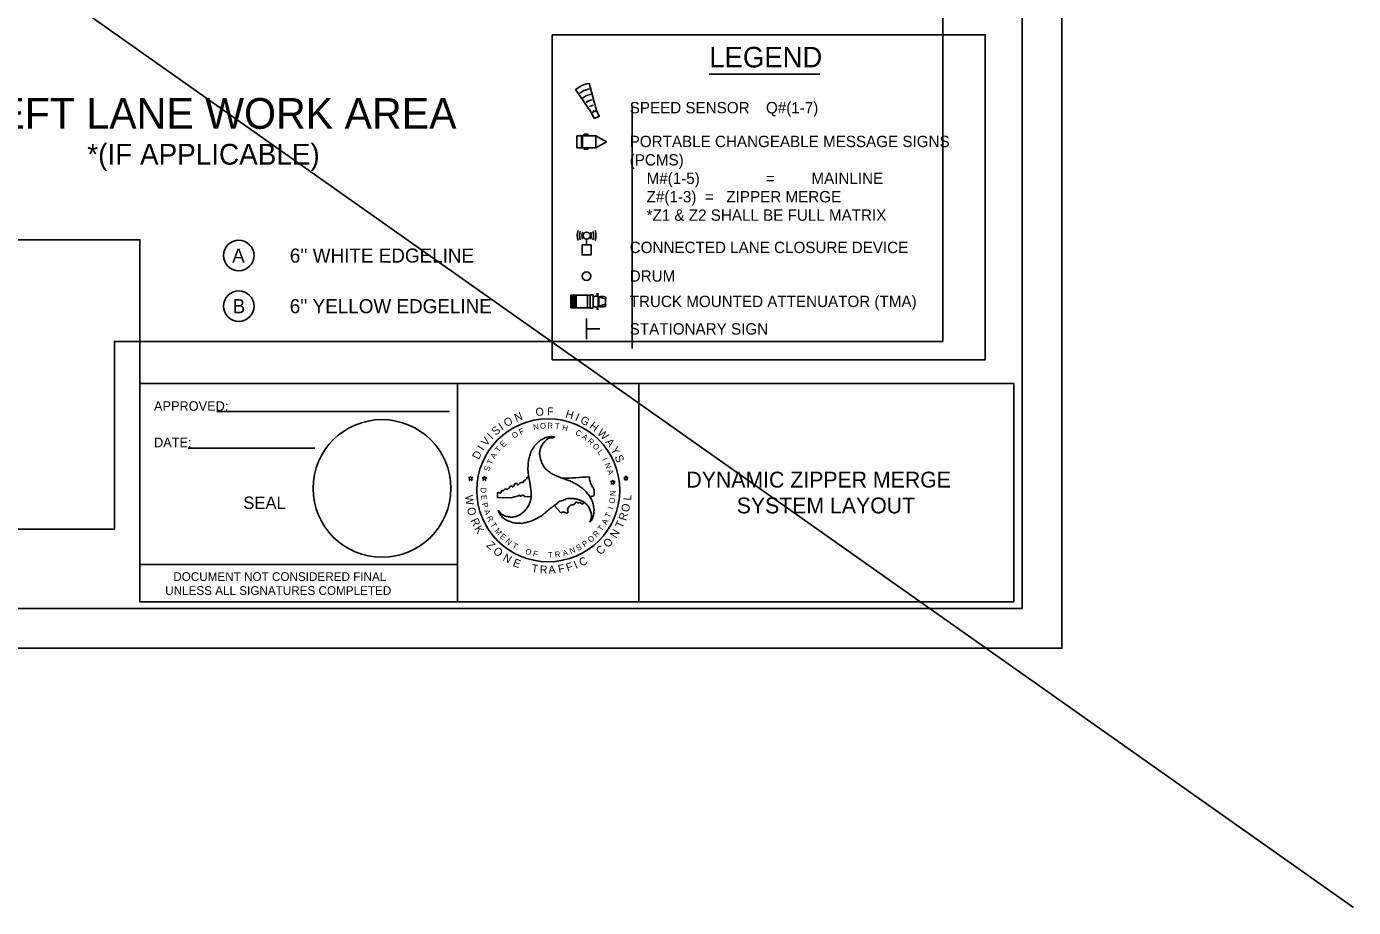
# Model space of a CAD drawing. Extents: x 1379436 to 1387057, y 792703 to 795604.
# Drawn here: x 1381631 to 1382883, y 792987 to 793820 of the extents above; entities that cross this region are included whole.
import ezdxf

# ---------------------------------------------------------------- set-up
doc = ezdxf.new("R2010")
doc.units = 0
for name, color, linetype in [('Black Area Fill Shapes', 7, 'Continuous'), ('Default', 7, 'Continuous'), ('DEV BORDER CELL', 7, 'Continuous'), ('DEV CMS PLAN VIEW CELL', 7, 'Continuous'), ('DEV DOT SWIRL SEAL CELL', 7, 'Continuous'), ('DEV DRUM PLAN VIEW CELL', 7, 'Continuous'), ('DEV PRELIMINARY STAMP CELL', 7, 'Continuous'), ('DEV TRUCK MOUNTED IMPACT ATTENUATOR CELL', 7, 'Continuous'), ('Scratch_Level_0', 7, 'Continuous'), ('Sheet Plot Border Outside CELL', 7, 'Continuous'), ('Sheet Sticker Exception Certification CELL', 7, 'Continuous'), ('TCP Linework', 7, 'Continuous'), ('Text', 7, 'Continuous')]:
    doc.layers.add(name, color=color, linetype=linetype)

msp = doc.modelspace()

# ---------------------------------------------------------------- linework, layer by layer
at = {"layer": 'Black Area Fill Shapes'}
msp.add_lwpolyline([(1382166.8, 793732.5), (1382164.2, 793738), (1382169, 793740.2), (1382171.6, 793734.7)], close=True, dxfattribs=at)
at = {"layer": 'Default'}
for p, q in [((1379436.3, 795421.7), (1382883.5, 792987.4)), ((1380320.7, 793618), (1381738.3, 793618)), ((1381738, 793482.4), (1381738, 793618))]:
    msp.add_line(p, q, dxfattribs=at)
for centre in [(1381831.4, 793603.2), (1381831.4, 793555.4)]:
    msp.add_circle(centre, 14.4, dxfattribs=at)
at = {"layer": 'DEV BORDER CELL'}
for p, q in [((1381810.8, 793455.8), (1382030.3, 793455.8)), ((1382038, 793447.1), (1382038, 793276.1)), ((1381783.6, 793421.2), (1381903.3, 793421.2))]:
    msp.add_line(p, q, dxfattribs=at)
for points in [[(1382570.8, 794844.7), (1380320.7, 794844.7), (1380320.7, 793269.7), (1382570.8, 793269.7)], [(1381738, 793482.4), (1382038, 793482.4), (1382038, 793276.1), (1381738, 793276.1)], [(1382038, 793482.4), (1382209, 793482.4), (1382209, 793276.1), (1382038, 793276.1)], [(1382563, 793482.4), (1382209, 793482.4), (1382209, 793276.1), (1382563, 793276.1)]]:
    msp.add_lwpolyline(points, close=True, dxfattribs=at)
msp.add_circle((1381966.6, 793383.2), 65, dxfattribs=at)
at = {"layer": 'DEV CMS PLAN VIEW CELL'}
for p, q in [((1382150.6, 793716.4), (1382168.4, 793716.4)), ((1382150.6, 793704.8), (1382150.6, 793716.4)), ((1382150.6, 793716.4), (1382150.6, 793704.8)), ((1382154.8, 793704.8), (1382154.8, 793716.4)), ((1382155.7, 793704.8), (1382155.7, 793716.4)), ((1382157.3, 793717.8), (1382161, 793717.8)), ((1382157.3, 793716.7), (1382161, 793716.7)), ((1382168.4, 793704.8), (1382168.4, 793716.4)), ((1382168.4, 793716.4), (1382178.4, 793710.6)), ((1382150.6, 793704.8), (1382168.4, 793704.8)), ((1382157.3, 793704.6), (1382161, 793704.6)), ((1382157.3, 793703.5), (1382161, 793703.5)), ((1382168.4, 793704.8), (1382178.4, 793710.6))]:
    msp.add_line(p, q, dxfattribs=at)
msp.add_circle((1382178.5, 793710.6), 0.102, dxfattribs=at)
for centre, start, end in [((1382158, 793717.3), 142.0883, 217.9117), ((1382160.3, 793717.3), 322.0883, 37.9117), ((1382158, 793704.1), 142.0883, 217.9117), ((1382160.3, 793704.1), 322.0883, 37.9117)]:
    msp.add_arc(centre, 0.852, start, end, dxfattribs=at)
at = {"layer": 'DEV DOT SWIRL SEAL CELL'}
for p, q in [((1382048.1, 793393.4), (1382049.4, 793392.4)), ((1382049.7, 793393.4), (1382048.1, 793393.4)), ((1382049.4, 793392.4), (1382049, 793390.8)), ((1382049, 793390.8), (1382050.2, 793391.8)), ((1382050.2, 793394.9), (1382049.7, 793393.4)), ((1382050.8, 793393.4), (1382050.2, 793394.9)), ((1382050.2, 793391.8), (1382051.6, 793390.8)), ((1382050.2, 793391.8), (1382051.6, 793390.8)), ((1382052.4, 793393.4), (1382050.8, 793393.4)), ((1382051.1, 793392.4), (1382052.4, 793393.4)), ((1382051.1, 793392.4), (1382052.4, 793393.4)), ((1382051.6, 793390.8), (1382051.1, 793392.4)), ((1382051.6, 793390.8), (1382051.1, 793392.4)), ((1382062.8, 793393.3), (1382061.1, 793393.3)), ((1382061.1, 793393.3), (1382062.5, 793392.4)), ((1382062.5, 793392.4), (1382062, 793390.8)), ((1382062, 793390.8), (1382063.2, 793391.8)), ((1382063.2, 793394.8), (1382062.8, 793393.3)), ((1382063.8, 793393.3), (1382063.2, 793394.8)), ((1382063.2, 793391.8), (1382064.6, 793390.8)), ((1382065.4, 793393.3), (1382063.8, 793393.3)), ((1382064.1, 793392.4), (1382065.4, 793393.3)), ((1382064.6, 793390.8), (1382064.1, 793392.4)), ((1382183.9, 793389.6), (1382182.3, 793389.6)), ((1382182.3, 793389.6), (1382183.6, 793388.6)), ((1382183.6, 793388.6), (1382183.1, 793387.1)), ((1382183.1, 793387.1), (1382184.4, 793388)), ((1382184.4, 793391.1), (1382183.9, 793389.6)), ((1382184.9, 793389.6), (1382184.4, 793391.1)), ((1382184.4, 793388), (1382185.7, 793387.1)), ((1382186.6, 793389.6), (1382184.9, 793389.6)), ((1382185.2, 793388.6), (1382186.6, 793389.6)), ((1382185.7, 793387.1), (1382185.2, 793388.6)), ((1382196.3, 793393.6), (1382194.7, 793393.6)), ((1382194.7, 793393.6), (1382196, 793392.6)), ((1382196, 793392.6), (1382195.5, 793391)), ((1382195.5, 793391), (1382196.8, 793392)), ((1382196.8, 793395.1), (1382196.3, 793393.6)), ((1382197.4, 793393.6), (1382196.8, 793395.1)), ((1382196.8, 793392), (1382198.1, 793391)), ((1382199, 793393.6), (1382197.4, 793393.6)), ((1382197.7, 793392.6), (1382199, 793393.6)), ((1382198.1, 793391), (1382197.7, 793392.6)), ((1382075.6, 793374.7), (1382075.7, 793378.7)), ((1382088.2, 793374.2), (1382075.6, 793374.7)), ((1382095.4, 793376.3), (1382088.2, 793374.2)), ((1382101, 793375.5), (1382107.3, 793375.4)), ((1382129.1, 793367.1), (1382135.5, 793360.1))]:
    msp.add_line(p, q, dxfattribs=at)
for start, end in [(265.6785, 265.9762), (271.2035, 275.3236)]:
    msp.add_arc((1382129.7, 793742.5), 349.8, start, end, dxfattribs=at)
for points in [[(1382076.2, 793362.5), (1382078.8, 793359.5), (1382082.1, 793357.4), (1382085.9, 793356.4), (1382090.1, 793356.2), (1382094.4, 793357.2), (1382097.2, 793358.7), (1382098.5, 793359.6), (1382100.5, 793361.3), (1382102, 793362.9), (1382104.5, 793366.4), (1382106.5, 793370.6), (1382107.3, 793375.4), (1382107.3, 793375.8), (1382107.3, 793380.3), (1382106.7, 793384.9), (1382106, 793389.3), (1382105.2, 793393.8), (1382104.5, 793398.3), (1382104.4, 793402.7), (1382104.7, 793407.7), (1382105.4, 793412), (1382106.8, 793416.5), (1382107.6, 793418.6), (1382108.6, 793420.3), (1382111.3, 793424.2), (1382114.7, 793427.5), (1382116.9, 793429.2), (1382119.1, 793430.3), (1382119.4, 793430.5), (1382123.7, 793431.9), (1382127.9, 793432), (1382129.3, 793431.7)], [(1382129.4, 793431.8), (1382129.3, 793431.7), (1382125.4, 793430.9), (1382121.9, 793429.1), (1382119.2, 793426.4), (1382116.9, 793422.9), (1382115.6, 793418.6), (1382115.4, 793415.4), (1382115.7, 793413.9), (1382116.1, 793411.2), (1382116.7, 793409.2), (1382118.6, 793405.2), (1382121.2, 793401.5), (1382125, 793398.4), (1382125.3, 793398.1), (1382129.2, 793395.9), (1382133.5, 793394.1), (1382137.6, 793392.5), (1382141.9, 793391), (1382146.2, 793389.3), (1382150, 793387.2), (1382154.3, 793384.4), (1382157.6, 793381.6), (1382160.7, 793378.2), (1382162.2, 793376.5), (1382163.1, 793374.7), (1382165.3, 793370.5), (1382166.3, 793365.9), (1382166.7, 793363.1), (1382166.6, 793360.7), (1382166.6, 793360.3), (1382165.6, 793355.9), (1382163.6, 793352.2), (1382162.7, 793351.2)], [(1382075.7, 793378.7), (1382075.6, 793379.1), (1382076.3, 793379.5), (1382078.2, 793378.7), (1382079.1, 793379.5), (1382079, 793380.3), (1382079.8, 793381.1), (1382081.1, 793380.9), (1382082.2, 793382.3), (1382083.3, 793382.6), (1382085.5, 793382.6), (1382088.2, 793385.3), (1382089.3, 793385.5), (1382089.6, 793384.7), (1382090.3, 793384.6), (1382091.5, 793386.8), (1382091.8, 793387.1), (1382093.8, 793388), (1382094.3, 793387.5), (1382094.5, 793386.6), (1382094.8, 793386.4), (1382095.5, 793386.9), (1382096.4, 793388), (1382098.1, 793388.9), (1382100.1, 793388.7), (1382100.4, 793390.3), (1382102.7, 793391.8), (1382103.2, 793392.7), (1382103.3, 793393.7)], [(1382162.6, 793375.8), (1382166.3, 793376.3), (1382166.8, 793379.2), (1382166.9, 793381.7), (1382165.3, 793384.5), (1382163.1, 793389.7), (1382162.1, 793394.2)], [(1382162.7, 793351.2), (1382164, 793354.9), (1382164.2, 793358.8), (1382163.1, 793362.5), (1382161.2, 793366.3), (1382158.2, 793369.5), (1382155.6, 793371.3), (1382154.1, 793371.8), (1382151.6, 793372.8), (1382149.4, 793373.3), (1382145.2, 793373.7), (1382140.5, 793373.3), (1382136, 793371.5), (1382135.6, 793371.4), (1382131.8, 793369.1), (1382128.1, 793366.3), (1382124.6, 793363.6), (1382121.1, 793360.6), (1382117.5, 793357.7), (1382113.8, 793355.4), (1382109.2, 793353.1), (1382105.2, 793351.7), (1382100.7, 793350.6), (1382098.4, 793350.2), (1382096.4, 793350.3), (1382091.7, 793350.6), (1382087.2, 793351.9), (1382084.6, 793353), (1382082.6, 793354.3), (1382082.2, 793354.5), (1382078.9, 793357.6), (1382076.7, 793361.1), (1382076.2, 793362.5)], [(1382101, 793375.5), (1382100.4, 793376.5), (1382099.4, 793376.8), (1382098, 793376), (1382097, 793376.1), (1382095.9, 793376.9), (1382095.4, 793376.3)], [(1382135.5, 793360.1), (1382138.1, 793360.8), (1382140.2, 793360), (1382141.2, 793359.9), (1382142.1, 793360.5), (1382141.8, 793363.7), (1382142.5, 793365.2), (1382146, 793367.7), (1382148.1, 793368.2), (1382149.7, 793370.1), (1382150.3, 793370.1), (1382151.3, 793369.5), (1382153.4, 793369.9), (1382155.2, 793368.5), (1382156.2, 793368.6), (1382157, 793370.2)]]:
    msp.add_spline(points, degree=3, dxfattribs=at)
at = {"layer": 'DEV DRUM PLAN VIEW CELL'}
msp.add_circle((1382159.7, 793583.7), 4.08, dxfattribs=at)
msp.add_circle((1382159.7, 793583.7), 4.08, dxfattribs=at)
at = {"layer": 'DEV TRUCK MOUNTED IMPACT ATTENUATOR CELL'}
for p, q in [((1382144.7, 793565.6), (1382163.2, 793565.6)), ((1382144.7, 793553.7), (1382144.7, 793565.6)), ((1382144.7, 793565.6), (1382144.7, 793563.4)), ((1382144.7, 793565.6), (1382144.7, 793563.4)), ((1382144.7, 793565.6), (1382144.7, 793563.4)), ((1382144.7, 793565.6), (1382144.7, 793563.4)), ((1382144.7, 793563.4), (1382144.7, 793565.6)), ((1382144.7, 793565.6), (1382146.8, 793565.6)), ((1382146.8, 793565.6), (1382144.7, 793563.4)), ((1382144.7, 793561.5), (1382148.4, 793565.6)), ((1382150, 793565.6), (1382144.7, 793559.7)), ((1382144.7, 793559.7), (1382144.7, 793561.5)), ((1382146.4, 793559.7), (1382150, 793563.8)), ((1382150, 793561.9), (1382148, 793559.7)), ((1382148.4, 793565.6), (1382150, 793565.6)), ((1382150, 793553.7), (1382150, 793565.6)), ((1382150, 793563.8), (1382150, 793561.9)), ((1382160.7, 793559.7), (1382160.7, 793565.6)), ((1382163.2, 793559.7), (1382163.2, 793565.6)), ((1382166, 793559.7), (1382166, 793565.6)), ((1382169.8, 793566), (1382169.8, 793567.5)), ((1382170.1, 793564.6), (1382170.1, 793567.5)), ((1382170.3, 793564.6), (1382170.3, 793567.5)), ((1382170.7, 793559.7), (1382170.7, 793564)), ((1382171.2, 793564), (1382177.6, 793562.2)), ((1382171.2, 793559.7), (1382171.2, 793564)), ((1382177.6, 793559.7), (1382177.6, 793562.2)), ((1382144.7, 793559.7), (1382150, 793553.7)), ((1382144.7, 793557.9), (1382144.7, 793559.7)), ((1382148.4, 793553.7), (1382144.7, 793557.9)), ((1382144.7, 793556), (1382144.7, 793553.7)), ((1382146.8, 793553.7), (1382144.7, 793556)), ((1382144.7, 793553.7), (1382163.2, 793553.7)), ((1382144.7, 793553.7), (1382146.8, 793553.7)), ((1382150, 793555.6), (1382146.4, 793559.7)), ((1382148.1, 793559.7), (1382150, 793557.5)), ((1382150, 793553.7), (1382148.4, 793553.7)), ((1382150, 793557.5), (1382150, 793555.6)), ((1382160.7, 793559.7), (1382160.7, 793553.7)), ((1382163.2, 793559.7), (1382163.2, 793553.7)), ((1382166, 793559.7), (1382166, 793553.7)), ((1382169.8, 793553.3), (1382169.8, 793551.9)), ((1382170.1, 793554.8), (1382170.1, 793551.9)), ((1382170.3, 793554.8), (1382170.3, 793551.9)), ((1382170.7, 793559.7), (1382170.7, 793555.4)), ((1382171.2, 793559.7), (1382171.2, 793555.4)), ((1382171.2, 793555.4), (1382177.6, 793557.2)), ((1382177.6, 793559.7), (1382177.6, 793557.2))]:
    msp.add_line(p, q, dxfattribs=at)
for centre in [(1382176, 793563.1), (1382176, 793556.3)]:
    msp.add_arc(centre, 1.79, 331.8801, 28.1199, dxfattribs=at)
for centre, major_axis, ratio, start_param, end_param in [((1382164.6, 793565.6), (1.41, 0), 0.269913, 6.283185, 9.424778), ((1382168.4, 793563.7), (2.37, 0.29), 0.503092, 0, 3.141593), ((1382174.4, 793563.9), (3.23, -0.04), 0.2034, 6.283185, 9.424778), ((1382164.6, 793553.7), (1.41, 0), 0.269913, 3.141593, 6.283185), ((1382168.4, 793555.7), (2.37, -0.29), 0.503092, 3.141593, 6.283185), ((1382174.4, 793555.4), (3.23, 0.04), 0.2034, 3.141593, 6.283185)]:
    msp.add_ellipse(centre, major_axis=major_axis, ratio=ratio, start_param=start_param, end_param=end_param, dxfattribs=at)
at = {"layer": 'Scratch_Level_0'}
msp.add_line((1382202.6, 793515.5), (1382202.6, 793745), dxfattribs=at)
msp.add_lwpolyline([(1382495.8, 794769.7), (1380395.7, 794769.7), (1380395.7, 793344.7), (1381714, 793344.7), (1381714, 793522.1), (1382495.8, 793522.1)], close=True, dxfattribs=at)
at = {"layer": 'Sheet Plot Border Outside CELL'}
msp.add_lwpolyline([(1380076.3, 793232.2), (1382608.3, 793232.2), (1382608.3, 794882.2), (1380076.3, 794882.2)], close=True, dxfattribs=at)
at = {"layer": 'Sheet Sticker Exception Certification CELL'}
for p, q in [((1381738, 793276.1), (1381738, 793311.4)), ((1381738, 793311.4), (1382038, 793311.4)), ((1382038, 793311.3), (1382038, 793276.1)), ((1382038, 793276.1), (1381738, 793276.1))]:
    msp.add_line(p, q, dxfattribs=at)
at = {"layer": 'TCP Linework'}
for p, q in [((1382159.7, 793543.6), (1382159.7, 793524.3)), ((1382159.7, 793533.9), (1382172.2, 793533.9))]:
    msp.add_line(p, q, dxfattribs=at)
msp.add_lwpolyline([(1382127.3, 793811.7), (1382536, 793811.7), (1382536, 793504.7), (1382127.3, 793504.7)], close=True, dxfattribs=at)
at = {"layer": 'Text'}
for p, q in [((1382275.5, 793774.4), (1382379.7, 793774.4)), ((1382169, 793740.2), (1382162, 793765.9)), ((1382164.2, 793738), (1382149.3, 793760)), ((1382159.7, 793613.2), (1382159.7, 793618.7))]:
    msp.add_line(p, q, dxfattribs=at)
msp.add_lwpolyline([(1382155.5, 793613.2), (1382163.9, 793613.2), (1382163.9, 793603.7), (1382155.5, 793603.7)], close=True, dxfattribs=at)
for centre, radius in [((1382159.7, 793622), 3.3), ((1382123.5, 793381.4), 67.5)]:
    msp.add_circle(centre, radius, dxfattribs=at)
for centre, radius, start, end in [((1382167.1, 793738), 28.3, 100.4731, 129.0092), ((1382167.1, 793738), 23.1, 100.4731, 129.0092), ((1382167.1, 793738), 17.9, 100.4731, 129.0092), ((1382167.1, 793738), 12.6, 100.4731, 129.0092), ((1382167.1, 793738), 7.36, 100.4731, 129.0092), ((1382167.1, 793738), 2.12, 100.4731, 129.0092), ((1382165.5, 793622), 14.6, 161.0657, 198.9343), ((1382165.5, 793622), 12.4, 161.0657, 198.9343), ((1382165.5, 793622), 10.2, 161.0657, 198.9343), ((1382153.9, 793622), 10.2, 341.0657, 18.9343), ((1382153.9, 793622), 12.4, 341.0657, 18.9343), ((1382153.9, 793622), 14.6, 341.0657, 18.9343)]:
    msp.add_arc(centre, radius, start, end, dxfattribs=at)

# ---------------------------------------------------------------- texts
at = {"layer": 'Default'}
for s, height, p in [('LEFT LANE WORK AREA', 29.027, (1381581.9, 793722.9)), ('*(IF APPLICABLE)', 19.675, (1381688.5, 793689)), ('DYNAMIC ZIPPER MERGE', 15, (1382253.9, 793384)), ('SYSTEM LAYOUT', 15, (1382301.4, 793359.6))]:
    msp.add_text(s, height=height, dxfattribs=at).set_placement(p)
at = {"layer": 'DEV BORDER CELL'}
for s, p in [('APPROVED:  ', (1381751.4, 793456.5)), ('DATE:  ', (1381751.4, 793422.1))]:
    msp.add_text(s, height=9, dxfattribs=at).set_placement(p)
at = {"layer": 'DEV DOT SWIRL SEAL CELL'}
for s, height, rotation, p in [('O', 7.56, 30.0935, (1382084.1, 793440.9)), ('N', 7.56, 21.5861, (1382093.3, 793445.9)), ('O', 7.56, 5.7649, (1382111.9, 793451.5)), ('F', 7.56, 357.2575, (1382122.3, 793452.3)), ('H', 7.56, 343.454, (1382139.2, 793450.4)), ('I', 7.56, 335.804, (1382148.2, 793447.6)), ('G', 7.56, 331.5167, (1382153, 793445.5)), ('I', 7.56, 44.8722, (1382070.4, 793429.1)), ('S', 7.56, 40.5848, (1382074, 793432.8)), ('I', 7.56, 34.3808, (1382079.8, 793437.8)), ('O', 5.44, 29.335, (1382091, 793430.1)), ('F', 5.44, 24.2569, (1382097.4, 793433.7)), ('N', 5.44, 9.0227, (1382109.7, 793438.3)), ('O', 5.44, 3.9446, (1382115.9, 793439.4)), ('R', 5.44, 358.8665, (1382122.6, 793439.8)), ('H', 5.44, 343.6322, (1382136.2, 793438.5)), ('C', 5.44, 333.4761, (1382148.6, 793434.2)), ('H', 7.56, 323.4632, (1382161.7, 793440.6)), ('W', 7.56, 315.8133, (1382169.2, 793434.9)), ('I', 7.56, 55.8679, (1382062.3, 793418.2)), ('V', 7.56, 51.5806, (1382065.2, 793422.6)), ('T', 5.44, 49.6473, (1382076.8, 793416.6)), ('E', 5.44, 44.5692, (1382081.1, 793421.6)), ('A', 5.44, 323.3199, (1382154.7, 793431)), ('R', 5.44, 318.2418, (1382160, 793427.1)), ('O', 5.44, 313.1637, (1382164.8, 793422.8)), ('A', 7.56, 306.7762, (1382176.9, 793427)), ('Y', 7.56, 299.7484, (1382182.1, 793420)), ('D', 7.56, 63.459, (1382058, 793409.9)), ('T', 5.44, 64.8816, (1382070.1, 793405)), ('A', 5.44, 59.8035, (1382073, 793410.7)), ('L', 5.44, 308.0856, (1382169.6, 793417.3)), ('I', 5.44, 297.9295, (1382174.2, 793410.5)), ('S', 7.56, 293.2249, (1382186, 793413)), ('S', 5.44, 69.9597, (1382067.7, 793398.8)), ('N', 5.44, 292.8514, (1382176.5, 793406.1)), ('A', 5.44, 287.7733, (1382178.9, 793400.1)), ('D', 5.44, 270.272, (1382059.7, 793384)), ('E', 5.44, 275.3501, (1382059.9, 793376.7)), ('O', 5.44, 82.9269, (1382186.2, 793368.6)), ('N', 5.44, 87.733, (1382187.2, 793375.9)), ('P', 5.44, 285.5063, (1382060.8, 793368.9)), ('A', 5.44, 290.5843, (1382062.6, 793362.2)), ('T', 5.44, 67.6926, (1382181.6, 793354.9)), ('I', 5.44, 72.7707, (1382184.6, 793363)), ('R', 5.44, 295.6624, (1382065.1, 793355.7)), ('T', 5.44, 300.7405, (1382068.5, 793349.1)), ('T', 5.44, 52.4584, (1382173.9, 793342.2)), ('A', 5.44, 62.6145, (1382178.3, 793348.4)), ('M', 5.44, 310.8967, (1382072.4, 793342.9)), ('E', 5.44, 315.9748, (1382077.4, 793337.2)), ('N', 5.44, 321.0529, (1382082.6, 793332.5)), ('O', 5.44, 42.3022, (1382163.7, 793331.7)), ('R', 5.44, 47.3803, (1382169, 793336.6)), ('T', 5.44, 331.209, (1382088.9, 793327.6)), ('O', 5.44, 341.3652, (1382101.3, 793321.6)), ('F', 5.44, 346.4433, (1382108.6, 793319.4)), ('T', 5.44, 1.6775, (1382123.3, 793317.6)), ('R', 5.44, 6.7556, (1382130, 793317.9)), ('A', 5.44, 16.9118, (1382137.9, 793319.1)), ('N', 5.44, 21.9899, (1382144.8, 793321.2)), ('S', 5.44, 27.068, (1382151.4, 793324)), ('P', 5.44, 32.146, (1382157.6, 793327.4))]:
    msp.add_text(s, height=height, rotation=rotation, dxfattribs=at).set_placement(p)
at = {"layer": 'DEV PRELIMINARY STAMP CELL'}
msp.add_text('SEAL', height=11.72, dxfattribs=at).set_placement((1381835.7, 793363.8))
at = {"layer": 'Sheet Sticker Exception Certification CELL'}
for s, p in [('DOCUMENT NOT CONSIDERED FINAL', (1381769.6, 793295.8)), ('UNLESS ALL SIGNATURES COMPLETED', (1381762, 793282.6))]:
    msp.add_text(s, height=8.25, dxfattribs=at).set_placement(p)
at = {"layer": 'Text'}
for s, height, p in [('LEGEND', 19.39, (1382275.5, 793780.9)), ('SPEED SENSOR', 10.722, (1382200.4, 793737.5)), ('Q#(1-7)', 10.72, (1382329, 793737.5)), ('PORTABLE CHANGEABLE MESSAGE SIGNS ', 10.722, (1382200.4, 793705.6)), ('(PCMS)', 10.72, (1382200.4, 793688.2)), ('    M#(1-5)', 10.722, (1382200.4, 793670.8)), ('=', 10.7, (1382329, 793670.8)), ('MAINLINE', 10.72, (1382371.9, 793670.8)), ('    Z#(1-3)  =   ZIPPER MERGE', 10.722, (1382200.4, 793653.4)), ('    *Z1 & Z2 SHALL BE FULL MATRIX    ', 10.722, (1382200.4, 793636)), ('CONNECTED LANE CLOSURE DEVICE', 10.722, (1382200.4, 793605.5)), ('A', 13.3, (1381825.2, 793596.5)), ("6'' WHITE EDGELINE", 13.31, (1381879.6, 793596.5)), ('DRUM', 10.72, (1382200.4, 793578.5)), ('B', 13.3, (1381825.7, 793548.7)), ("6'' YELLOW EDGELINE", 13.31, (1381879.5, 793548.7)), ('TRUCK MOUNTED ATTENUATOR (TMA)', 10.722, (1382200.4, 793554.5)), ('STATIONARY SIGN', 10.722, (1382200.4, 793528.5))]:
    msp.add_text(s, height=height, dxfattribs=at).set_placement(p)
for s, height, rotation, p in [('T', 5.44, 353.7884, (1382129.6, 793439.5)), ('W', 7.56, 278.15, (1382044.8, 793376.4)), ('L', 7.56, 87.429, (1382201.8, 793371.7)), ('O', 7.56, 287.1147, (1382046.5, 793364.2)), ('R', 7.56, 72.7519, (1382196.8, 793352.2)), ('O', 7.56, 78.9896, (1382199.6, 793360.4)), ('R', 7.56, 295.5541, (1382049.9, 793353)), ('K', 7.56, 301.7918, (1382053.4, 793345.2)), ('T', 7.56, 66.881, (1382193.4, 793344.9)), ('O', 7.56, 50.4526, (1382180.3, 793326.6)), ('N', 7.56, 58.892, (1382187.7, 793335.5)), ('Z', 7.56, 316.1688, (1382064.6, 793328.9)), ('O', 7.56, 322.5233, (1382070.8, 793322.7)), ('C', 7.56, 43.0807, (1382172.8, 793319.8)), ('N', 7.56, 330.9626, (1382080, 793315.6)), ('E', 7.56, 338.9517, (1382089.5, 793310.2)), ('T', 7.56, 352.6948, (1382107.4, 793304.2)), ('R', 7.56, 358.5656, (1382115.4, 793302.9)), ('A', 7.56, 4.8034, (1382124, 793302.5)), ('F', 7.56, 11.7751, (1382133.6, 793303.2)), ('F', 7.56, 17.7627, (1382141.7, 793304.6)), ('I', 7.56, 23.7503, (1382149.6, 793307)), ('C', 7.56, 28.0033, (1382155, 793309.1))]:
    msp.add_text(s, height=height, rotation=rotation, dxfattribs=at).set_placement(p)

doc.saveas('drawing.dxf')
